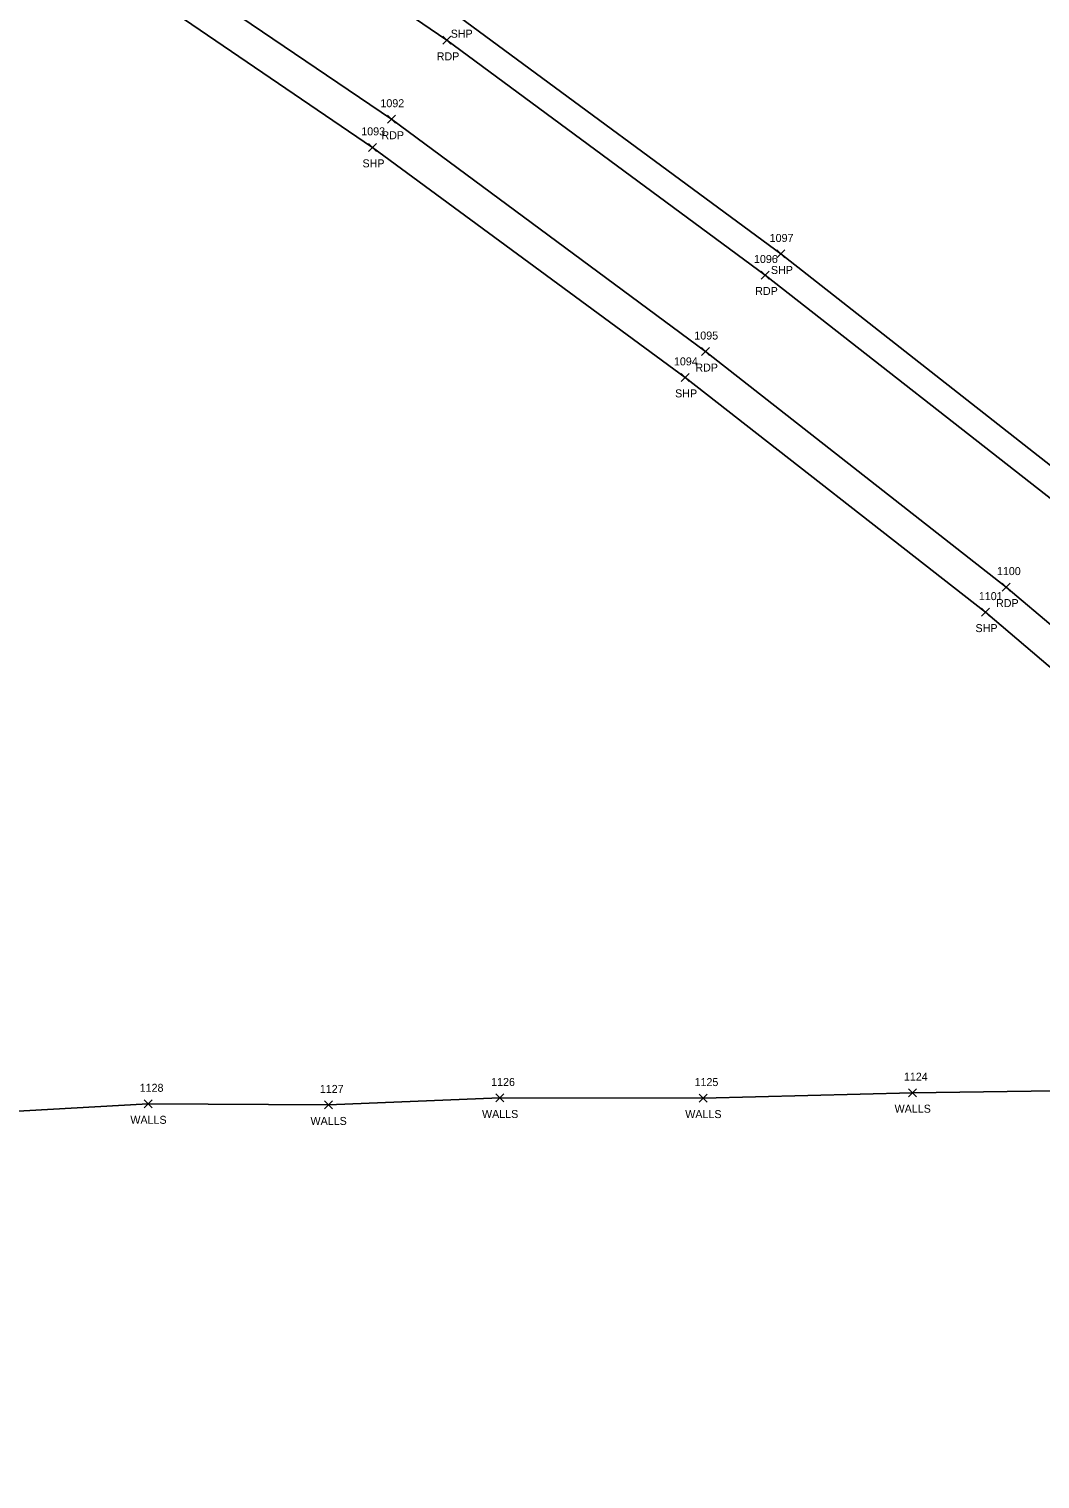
# Model space of a CAD drawing. Extents: x 1519347 to 1522636, y 378779 to 379832.
# Drawn here: x 1522127.4 to 1522380.1, y 378813.2 to 379175.6 of the extents above; entities that cross this region are included whole.
import ezdxf

# ---------------------------------------------------------------- set-up
doc = ezdxf.new("R2010")
doc.units = 0
for name, color, linetype in [('L_A', 7, 'Continuous'), ('L_I', 7, 'Continuous'), ('L_TIC', 7, 'Continuous'), ('LWS', 7, 'Continuous'), ('P_A', 7, 'Continuous'), ('P_I', 7, 'Continuous'), ('P_TIC', 7, 'Continuous'), ('PE', 7, 'Continuous'), ('PSP', 7, 'Continuous')]:
    doc.layers.add(name, color=color, linetype=linetype)

msp = doc.modelspace()

# ---------------------------------------------------------------- linework, layer by layer
at = {"layer": 'L_TIC'}
for points in [[(1522244.08, 378907.42), (1522246.08, 378909.42)], [(1522246.08, 378907.42), (1522244.08, 378909.42)], [(1522294.88, 378907.39), (1522296.88, 378909.39)], [(1522296.88, 378907.39), (1522294.88, 378909.39)], [(1522347.21, 378908.74), (1522349.21, 378910.74)], [(1522349.21, 378908.74), (1522347.21, 378910.74)], [(1522156.16, 378905.96), (1522158.16, 378907.96)], [(1522158.16, 378905.96), (1522156.16, 378907.96)], [(1522201.2, 378905.68), (1522203.2, 378907.68)], [(1522203.2, 378905.68), (1522201.2, 378907.68)]]:
    msp.add_lwpolyline(points, dxfattribs=at)
at = {"layer": 'LWS'}
msp.add_lwpolyline([(1522445.31, 378910.72), (1522401.54, 378910.43), (1522348.21, 378909.74), (1522295.88, 378908.39), (1522245.08, 378908.42), (1522202.2, 378906.68), (1522157.16, 378906.96), (1522120.07, 378904.84), (1522091.12, 378905.13), (1522034.79, 378905.64), (1521976.72, 378902.28), (1521929.9, 378901.52), (1521875.34, 378901.77), (1521835.92, 378899.64), (1521789.94, 378904.13), (1521732.75, 378904.41), (1521692.11, 378903.65), (1521648.67, 378903.93), (1521616.94, 378904.79), (1521567.34, 378904.32)], dxfattribs=at)
at = {"layer": 'P_TIC'}
for points in [[(1522230.81, 379171.75), (1522232.81, 379173.75)], [(1522232.81, 379171.75), (1522230.81, 379173.75)], [(1522216.99, 379152.03), (1522218.99, 379154.03)], [(1522218.99, 379152.03), (1522216.99, 379154.03)], [(1522212.2, 379145), (1522214.2, 379147)], [(1522214.2, 379145), (1522212.2, 379147)], [(1522314.3, 379118.36), (1522316.3, 379120.36)], [(1522316.3, 379118.36), (1522314.3, 379120.36)], [(1522310.43, 379113.1), (1522312.43, 379115.1)], [(1522312.43, 379113.1), (1522310.43, 379115.1)], [(1522295.46, 379093.97), (1522297.46, 379095.97)], [(1522297.46, 379093.97), (1522295.46, 379095.97)], [(1522290.37, 379087.51), (1522292.37, 379089.51)], [(1522292.37, 379087.51), (1522290.37, 379089.51)], [(1522370.63, 379035.1), (1522372.63, 379037.1)], [(1522372.63, 379035.1), (1522370.63, 379037.1)], [(1522365.45, 379028.85), (1522367.45, 379030.85)], [(1522367.45, 379028.85), (1522365.45, 379030.85)]]:
    msp.add_lwpolyline(points, dxfattribs=at)
at = {"layer": 'PE'}
for points in [[(1521529.39, 379535.32), (1521632.62, 379496.8), (1521722.31, 379458.96), (1521816.06, 379415.75), (1521903.5, 379372.19), (1521985.15, 379327.91), (1522068.34, 379279.51), (1522152.8, 379226.58), (1522231.81, 379172.75), (1522311.43, 379114.1), (1522387.62, 379054.41), (1522460.96, 378992.6), (1522530.24, 378930.24), (1522627.42, 378835.6)], [(1521521.96, 379512.45), (1521622.97, 379474.43), (1521713.3, 379436.47), (1521805.17, 379393.75), (1521891.16, 379351.25), (1521973.22, 379306.84), (1522055.83, 379258.59), (1522137.28, 379207.8), (1522217.99, 379153.03), (1522296.46, 379094.97), (1522371.63, 379036.1), (1522445.19, 378974.11), (1522514.07, 378912.19), (1522609.78, 378819.15)]]:
    msp.add_lwpolyline(points, dxfattribs=at)
at = {"layer": 'PSP'}
for points in [[(1521531.82, 379542.79), (1521635.1, 379503.97), (1521725.46, 379466.08), (1521819.09, 379422.88), (1521907.05, 379378.96), (1521988.73, 379335.06), (1522072.92, 379286.87), (1522157.1, 379232.77), (1522235.26, 379178.41), (1522315.3, 379119.36), (1522391.65, 379059.53), (1522465.18, 378997.47), (1522534.68, 378934.98), (1522631.83, 378840.12)], [(1521519.02, 379505.15), (1521619.86, 379467.25), (1521710.1, 379429.27), (1521802.41, 379386.84), (1521887.29, 379344.47), (1521969.86, 379299.81), (1522051.39, 379251.77), (1522132.8, 379200.77), (1522213.2, 379146), (1522291.37, 379088.51), (1522366.45, 379029.85), (1522439.83, 378967.41), (1522509.25, 378905.3), (1522537.61, 378878.43), (1522603.87, 378813.19)]]:
    msp.add_lwpolyline(points, dxfattribs=at)

# ---------------------------------------------------------------- texts
at = {"layer": 'L_A'}
for p in [(1522240.62, 378903.42), (1522291.42, 378903.39), (1522343.76, 378904.74), (1522152.71, 378901.96), (1522197.74, 378901.68)]:
    msp.add_text('WALLS', height=2, dxfattribs=at).set_placement(p)
at = {"layer": 'L_I'}
for s, p in [('1126', (1522242.9, 378911.42)), ('1125', (1522293.75, 378911.39)), ('1124', (1522346.09, 378912.74)), ('1128', (1522155.04, 378909.96)), ('1127', (1522200.07, 378909.68))]:
    msp.add_text(s, height=2, dxfattribs=at).set_placement(p)
at = {"layer": 'P_A'}
for s, p in [('SHP', (1522232.79, 379173.41)), ('RDP', (1522229.3, 379167.75)), ('RDP', (1522215.48, 379148.03)), ('SHP', (1522210.74, 379141)), ('SHP', (1522312.84, 379114.36)), ('RDP', (1522308.92, 379109.1)), ('RDP', (1522293.95, 379089.97)), ('SHP', (1522288.9, 379083.51)), ('RDP', (1522369.12, 379031.1)), ('SHP', (1522363.99, 379024.85))]:
    msp.add_text(s, height=2, dxfattribs=at).set_placement(p)
at = {"layer": 'P_I'}
for s, p in [('1092', (1522215.22, 379156.03)), ('1093', (1522210.43, 379149)), ('1097', (1522312.53, 379122.36)), ('1096', (1522308.61, 379117.1)), ('1095', (1522293.69, 379097.97)), ('1094', (1522288.6, 379091.51)), ('1100', (1522369.34, 379039.1)), ('1101', (1522364.82, 379032.85))]:
    msp.add_text(s, height=2, dxfattribs=at).set_placement(p)

doc.saveas('drawing.dxf')
